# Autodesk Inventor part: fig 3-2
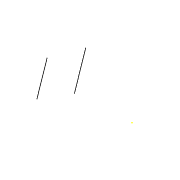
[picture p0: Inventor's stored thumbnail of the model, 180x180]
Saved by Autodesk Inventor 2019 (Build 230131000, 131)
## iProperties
Created: 2011-07
Part Number: fig 3-2
Material: Generic
Document SubType Name: Modeling
Designer: CadCim
Density: 1 g/cm^3
Appearance: Default
Author: CadCim
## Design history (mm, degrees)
sketch "Sketch1"
  geometry: L1 (-29, 4)-(-20, -8); L2 (-16, -0.965)-(-25.943, 12.292); 1 further point
  constraints: 4 end point, 1 parallel, 1 other
